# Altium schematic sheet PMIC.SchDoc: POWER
size A3; Author: Arturo Guadalupi; DocumentNumber: ABX00051; Revision: V1.1; SheetNumber: 2; SheetTotal: 3; RevAuthor: Silvio Navaretti
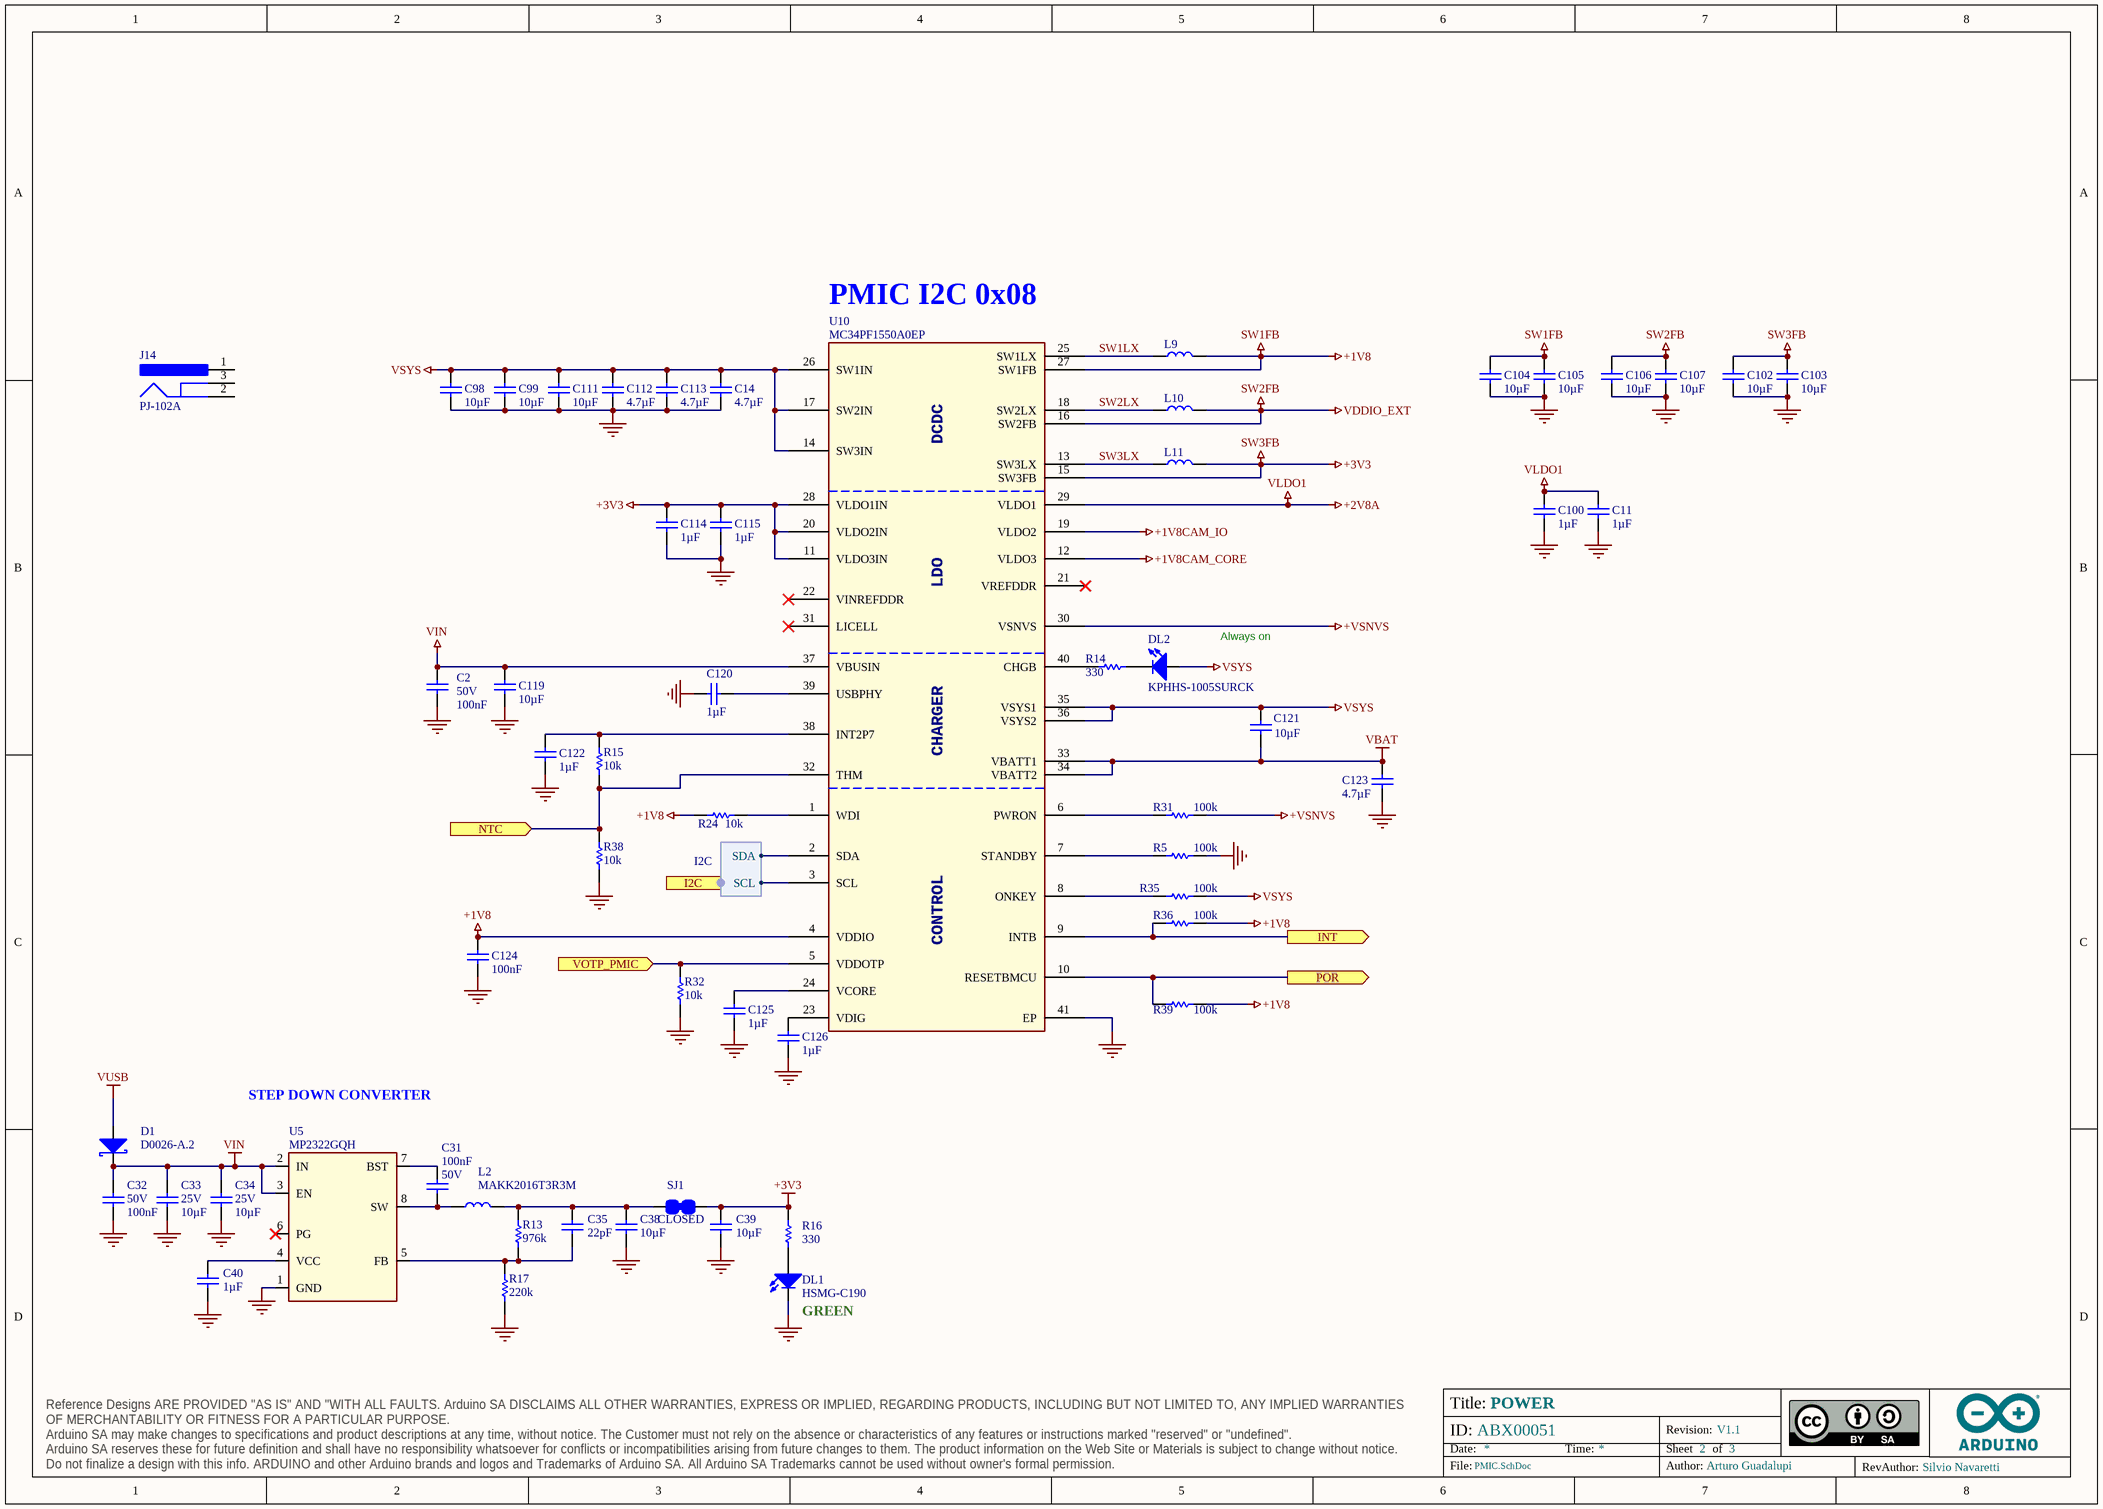
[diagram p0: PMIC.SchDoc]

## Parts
C2  value 100nF  Voltage: 50V  [CAP-0402]  (hidden comment: GRM155R61H104KE19D)
C11  value 1µF  [CAP-0402]  (hidden comment: C0402C105K8PACTU)
C14  value 4.7µF  [CAP-0402]  (hidden comment: GRM155R60J475ME47D)
C31  value 100nF  Voltage: 50V  [CAP-0402]  (hidden comment: GRM155R61H104KE19D)
C32  value 100nF  Voltage: 50V  [CAP-0402]  (hidden comment: GRM155R61H104KE19D)
C33  value 10µF  Voltage: 25V  [CAP-0603]  (hidden comment: GRM188R61E106MA73J)
C34  value 10µF  Voltage: 25V  [CAP-0603]  (hidden comment: GRM188R61E106MA73J)
C35  value 22pF  [CAP-0402]  (hidden comment: C0402C220J5GAC7411)
C38  value 10µF  [CAP-0603]  (hidden comment: GRM188R61E106MA73J)
C39  value 10µF  [CAP-0603]  (hidden comment: GRM188R61E106MA73J)
C40  value 1µF  [CAP-0402]  (hidden comment: C0402C105K8PACTU)
C98  value 10µF  [CAP-0402]  (hidden comment: GRM155R60J106ME05D)
C99  value 10µF  [CAP-0402]  (hidden comment: GRM155R60J106ME05D)
C100  value 1µF  [CAP-0402]  (hidden comment: C0402C105K8PACTU)
C102  value 10µF  [CAP-0402]  (hidden comment: GRM155R60J106ME05D)
C103  value 10µF  [CAP-0402]  (hidden comment: GRM155R60J106ME05D)
C104  value 10µF  [CAP-0402]  (hidden comment: GRM155R60J106ME05D)
C105  value 10µF  [CAP-0402]  (hidden comment: GRM155R60J106ME05D)
C106  value 10µF  [CAP-0402]  (hidden comment: GRM155R60J106ME05D)
C107  value 10µF  [CAP-0402]  (hidden comment: GRM155R60J106ME05D)
C111  value 10µF  [CAP-0402]  (hidden comment: GRM155R60J106ME05D)
C112  value 4.7µF  [CAP-0402]  (hidden comment: GRM155R60J475ME47D)
C113  value 4.7µF  [CAP-0402]  (hidden comment: GRM155R60J475ME47D)
C114  value 1µF  [CAP-0402]  (hidden comment: C0402C105K8PACTU)
C115  value 1µF  [CAP-0402]  (hidden comment: C0402C105K8PACTU)
C119  value 10µF  [CAP-0402]  (hidden comment: GRM155R60J106ME05D)
C120  value 1µF  [CAP-0402]  (hidden comment: C0402C105K8PACTU)
C121  value 10µF  [CAP-0402]  (hidden comment: GRM155R60J106ME05D)
C122  value 1µF  [CAP-0402]  (hidden comment: C0402C105K8PACTU)
C123  value 4.7µF  [CAP-0402]  (hidden comment: GRM155R60J475ME47D)
C124  value 100nF  [CAP-0402]  (hidden comment: GRM155R61H104KE19D)
C125  value 1µF  [CAP-0402]  (hidden comment: C0402C105K8PACTU)
C126  value 1µF  [CAP-0402]  (hidden comment: C0402C105K8PACTU)
D1  D0026-A.2  [SOD123-1]
DL1  HSMG-C190  [LEDC1608X80N-AK]
DL2  KPHHS-1005SURCK  [0402-LED]
J14  PJ-102A  [CUI-PJ-102A_V]
L2  MAKK2016T3R3M  [MAKK2016T3R3M-Footprint-1]
L9  DFE201610P-1R0M=P2  [IND-0806]  (value not drawn)
L10  DFE201610P-1R0M=P2  [IND-0806]  (value not drawn)
L11  DFE201610P-1R0M=P2  [IND-0806]  (value not drawn)
R5  value 100k  [RES-0402]  (hidden comment: CRCW0402100KFKEDC)
R13  value 976k  [RES-0402]  (hidden comment: CRCW0402976KFKED)
R14  value 330  [RES-0402]  (hidden comment: CRCW0402330RJNED)
R15  value 10k  [RES-0402]  (hidden comment: CRCW040210K0FKED)
R16  value 330  [RES-0402]  (hidden comment: CRCW0402330RJNED)
R17  value 220k  [RES-0402]  (hidden comment: CRCW0402220KFKED)
R24  value 10k  [RES-0402]  (hidden comment: CRCW040210K0FKED)
R31  value 100k  [RES-0402]  (hidden comment: CRCW0402100KFKEDC)
R32  value 10k  [RES-0402]  (hidden comment: CRCW040210K0FKED)
R35  value 100k  [RES-0402]  (hidden comment: CRCW0402100KFKEDC)
R36  value 100k  [RES-0402]  (hidden comment: CRCW0402100KFKEDC)
R38  value 10k  [RES-0402]  (hidden comment: CRCW040210K0FKED)
R39  value 100k  [RES-0402]  (hidden comment: CRCW0402100KFKEDC)
SJ1  SMD solder JUMPER CLOSED  [SJ]  (value not drawn)  (no BOM)
U5  MP2322GQH  [QFN50P150X200X90-8L]
U10  MC34PF1550A0EP  [QFN40P500X500X90_HS-41L]

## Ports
I2C (harness I2C), INT (out), NTC (in), POR (out), VOTP_PMIC (in)

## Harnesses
I2C: SDA, SCL

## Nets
+1V8: C104.2 C105.2 C124.2 L9.2 R24.1 R36.1 R39.1 U10.4(VDDIO) U10.27(SW1FB)  [also labelled SW1FB]
+1V8CAM_CORE: U10.12(VLDO3)
+1V8CAM_IO: U10.19(VLDO2)
+2V8A: C11.2 C100.2 U10.29(VLDO1)  [also labelled VLDO1]
+3V3: C39.2 C102.2 C103.2 C114.2 C115.2 L11.2 R16.2 SJ1.2 U10.11(VLDO3IN) U10.15(SW3FB) U10.20(VLDO2IN) U10.28(VLDO1IN)  [also labelled SW3FB]
+VSNVS: R31.1 U10.30(VSNVS)
GND: C2.2 C11.1 C14.1 C32.2 C33.1 C34.1 C38.1 C39.1 C40.1 C98.1 C99.1 C100.1 C102.1 C103.1 C104.1 C105.1 C106.1 C107.1 C111.1 C112.1 C113.1 C114.1 C115.1 C119.1 C120.1 C122.1 C123.1 C124.1 C125.1 C126.1 DL1.C R5.1 R17.1 R32.1 R38.2 U5.1(GND) U10.41(EP)
SW2FB: C106.2 C107.2 L10.2 U10.16(SW2FB)  [also labelled VDDIO_EXT]
VBAT: C121.1 C123.2 U10.33(VBATT1) U10.34(VBATT2)
VIN: C2.1 C32.1 C33.2 C34.2 C119.2 D1.C U5.2(IN) U5.3(EN) U10.37(VBUSIN)
VSYS: C14.2 C98.2 C99.2 C111.2 C112.2 C113.2 C121.2 DL2.A R35.1 U10.14(SW3IN) U10.17(SW2IN) U10.26(SW1IN) U10.35(VSYS1) U10.36(VSYS2)
VUSB: D1.A
INT: R36.2 U10.9(INTB) ; port INT
NTC: R15.2 R38.1 U10.32(THM) ; port NTC
POR: R39.2 U10.10(RESETBMCU) ; port POR
SW1LX: L9.1 U10.25(SW1LX)
SW2LX: L10.1 U10.18(SW2LX)
SW3LX: L11.1 U10.13(SW3LX)
VOTP_PMIC: R32.2 U10.5(VDDOTP) ; port VOTP_PMIC
NetC31_1: C31.1 L2.1 U5.8(SW)
NetC31_2: C31.2 U5.7(BST)
NetC35_1: C35.1 R13.1 R17.2 U5.5(FB)
NetC35_2: C35.2 C38.2 L2.2 R13.2 SJ1.1
NetC40_2: C40.2 U5.4(VCC)
NetC120_2: C120.2 U10.39(USBPHY)
NetC122_2: C122.2 R15.1 U10.38(INT2P7)
NetC125_2: C125.2 U10.24(VCORE)
NetC126_2: C126.2 U10.23(VDIG)
NetDL1_A: DL1.A R16.1
NetDL2_C: DL2.C R14.2
NetR5_2: R5.2 U10.7(STANDBY)
NetR14_1: R14.1 U10.40(CHGB)
NetR24_2: R24.2 U10.1(WDI)
NetR31_2: R31.2 U10.6(PWRON)
NetR35_2: R35.2 U10.8(ONKEY)
NetU10_2: U10.2(SDA) ; port I2C.SDA
NetU10_3: U10.3(SCL) ; port I2C.SCL

Not connected (* = marked no-connect by the designer): J14 1 2 3; U5 6(PG)*; U10 21(VREFDDR)* 22(VINREFDDR)* 31(LICELL)*

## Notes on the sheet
- (near U10) PMIC I2C 0x08
- Always on 3.0V
- STEP DOWN CONVERTER
- (near DL1) GREEN

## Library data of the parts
C2 C31 C32 C124 = C0015-A.9: CAP CHIP 0402 100nF 50V X5R 10%; Manufacturer: Murata; Code Arduino: A5141
C11 C40 C100 C114 C115 C120 C122 C125 C126 = C0017-A.9: CAP CHIP 0402 1uF 10V X5R 10%; Manufacturer: KEMET; Code Arduino: 0133
C14 C112 C113 C123 = C0037-A.9: CAP CHIP 0402 4.7uF 6V3 X5R 20%; Manufacturer: Murata; Code Arduino: 0833; Voltage: 6.3V
C33 C34 C38 C39 = C0047-A.13: CAP CHIP 0603 10uF 25V X5R 20%; Manufacturer: Murata; Code Arduino: 2213
C35 = C0029-A.9: CAP CHIP 0402 22pF 50V C0G 5%; Manufacturer: KEMET; Code Arduino: 0137
C98 C99 C102-C107 C111 C119 C121 = C0091-A.8: CAP CHIP 0402 10UF X5R 6.3V 20%; Manufacturer: Murata; Code Arduino: C0091
D1 = D0026-A.2: DIODE SCHOTTKY SMD 1A 40V SOD123FL; Manufacturer: Nexperia; Part Number: PMEG6020AELRX; Code Arduino: 2208
DL1 = L0009-A.4: LED SMD 0603 GREEN/568 15mcd 120^; Manufacturer: Broadcom; Code Arduino: 2204
DL2 = L0004-A.6: LED SMD 0402 RED630 220mcd 120^; Manufacturer: Kingbright; Code Arduino: A5160
J14 = J0083-A.5: CONN PWR JACK 2X5.5MM SOLDER; Manufacturer: CUI; Insulation Resistance: 50MR; Current Rating: 2.5A; Voltage Rating: 24V; Gender: Male; Shielding: Unshielded; Number of Conductors: 2; Code Arduino: J0083
L2 = I0045-A.7: IND CHIP 0806 3.3 uH 20% 1.2A; Manufacturer: Taiyo Yuden; Max DC Current: 1.15A; Core Material: Metal; DC Resistance (DCR): 255mR; Code Arduino: I0045; Test Frequency: 2MHz; Inductance: 3.3uH; Shielding: Shielded
L9-L11 = I0024-A.9: IND FIXED SMD 0806 1UH 3.1A 70 MOHM; Manufacturer: Murata; Max DC Current: 2.2A; Code Arduino: I0024; DC Resistance (DCR): 70mR; Test Frequency: 1MHz; Tolerance: 20%
R5 R31 R35 R36 R39 = R0001-A.8: RES CHIP 0402 100K 1% 1/16W; Manufacturer: Vishay; Power: 63mW; Code Arduino: 0134
R13 = R0070-A.9: RES CHIP 0402 976K 1% 1/16W; Manufacturer: Vishay; Power: 63mW; Code Arduino: R0070
R14 R16 = R0017-A.8: RES CHIP 0402 330R 5% 1/16W; Manufacturer: Vishay; Power: 63mW; Code Arduino: 2229
R15 R24 R32 R38 = R0003-A.8: RES CHIP 0402 10K 1% 1/16W; Manufacturer: Vishay; Power: 63mW; Code Arduino: 0136
R17 = R0028-A.8: RES CHIP 0402 220K 1% 1/16W; Manufacturer: Vishay; Code Arduino: 2334; Power: 63mW
SJ1 = UT0006-A.10: Solder Jumper shorted pads
U5 = U0072-A.5: IC STEP DOWN CONV 1A 22V QFN8; Manufacturer: Monolithic Power Systems; Code Arduino: U0072
U10 = U0068-A.6: IC PMIC 3LDO QFN40; Manufacturer: NXP; Code Arduino: U0068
